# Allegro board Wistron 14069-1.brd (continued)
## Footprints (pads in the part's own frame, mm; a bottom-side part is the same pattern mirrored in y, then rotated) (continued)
SKTBGA1151R754612-UH369
  round 0.254 hole 3.81 unplated: (-35.21,0) (25.81,18) (25.81,-18)
  round 0.508 smd: A4(-16.187,18.288) A5(-15.273,18.288) AT40(18.931,-14.63) AU1(-18.931,-14.63) AU39(18.016,-15.545) AU40(18.931,-15.545) AV1(-18.931,-15.545) AV2(-18.016,-15.545) AV38(17.102,-16.459) AV39(18.016,-16.459) AW2(-18.016,-16.459) AW3(-17.102,-16.459) AW37(16.187,-17.374) AW38(17.102,-17.374) AY3(-17.102,-17.374) AY4(-16.187,-17.374) B3(-17.102,17.374) B4(-16.187,17.374) B37(16.187,16.459) B38(17.102,16.459) B39(18.016,16.459) C2(-18.016,16.459) C3(-17.102,16.459) C39(18.016,15.545) C40(18.931,15.545) D1(-18.931,15.545) D2(-18.016,15.545) D40(18.931,14.63) E40(18.931,13.716)
  round 0.429 smd: A6(-14.359,18.288) A7(-13.444,18.288) A25(3.015,18.288) A26(3.929,18.288) A27(4.844,18.288) A28(5.758,18.288) A29(6.673,18.288) A30(7.587,18.288) AA5(-15.273,0) AA6(-14.359,0) AA7(-13.444,0) AA8(-12.53,0) AA33(12.53,-0.914) AA34(13.444,-0.914) AA35(14.359,-0.914) AA36(15.273,-0.914) AA37(16.187,-0.914) AA38(17.102,-0.914) AB5(-15.273,-0.914) AB6(-14.359,-0.914) AB7(-13.444,-0.914) AB8(-12.53,-0.914) AB33(12.53,-1.829) AB34(13.444,-1.829) AB35(14.359,-1.829) AB36(15.273,-1.829) AB37(16.187,-1.829) AC5(-15.273,-1.829) AC6(-14.359,-1.829) AC7(-13.444,-1.829) AC8(-12.53,-1.829) AC33(12.53,-2.743) AC34(13.444,-2.743) AC35(14.359,-2.743) AC36(15.273,-2.743) AC37(16.187,-2.743) AD3(-17.102,-2.743) AD4(-16.187,-2.743) AD5(-15.273,-2.743) AD6(-14.359,-2.743) AD7(-13.444,-2.743) AD8(-12.53,-2.743) AD33(12.53,-3.658) AD34(13.444,-3.658) AD35(14.359,-3.658) AD36(15.273,-3.658) AD37(16.187,-3.658) AE3(-17.102,-3.658) AE4(-16.187,-3.658) AE5(-15.273,-3.658) AE6(-14.359,-3.658) AE7(-13.444,-3.658) AE8(-12.53,-3.658) AE33(12.53,-4.572) AE34(13.444,-4.572) AE35(14.359,-4.572) AE36(15.273,-4.572) AE37(16.187,-4.572) AE38(17.102,-4.572) AF4(-16.187,-4.572) AF5(-15.273,-4.572) AF6(-14.359,-4.572) AF7(-13.444,-4.572) AF8(-12.53,-4.572) AF33(12.53,-5.486) AF34(13.444,-5.486) AF35(14.359,-5.486) AF36(15.273,-5.486) AF37(16.187,-5.486) AF38(17.102,-5.486) AG4(-16.187,-5.486) AG5(-15.273,-5.486) AG6(-14.359,-5.486) AG7(-13.444,-5.486) AG8(-12.53,-5.486) AG33(12.53,-6.401) AG34(13.444,-6.401) AG35(14.359,-6.401) AG36(15.273,-6.401) AG37(16.187,-6.401) AG38(17.102,-6.401) AH3(-17.102,-6.401) AH4(-16.187,-6.401) AH5(-15.273,-6.401) AH6(-14.359,-6.401) AH7(-13.444,-6.401) AH8(-12.53,-6.401) AH33(12.53,-7.315) AH34(13.444,-7.315) AH35(14.359,-7.315) AH36(15.273,-7.315) AH37(16.187,-7.315) AH38(17.102,-7.315) AJ3(-17.102,-7.315) AJ4(-16.187,-7.315) AJ5(-15.273,-7.315) AJ6(-14.359,-7.315) AJ7(-13.444,-7.315) AJ8(-12.53,-7.315) AJ9(-11.615,-7.315) AJ11(-7.587,-8.23) AJ12(-6.673,-8.23) AJ13(-5.758,-8.23) AJ14(-4.844,-8.23) AJ15(-3.929,-8.23) AJ16(-3.015,-8.23) AJ17(-2.101,-8.23) AJ18(-1.186,-8.23) AJ19(-0.272,-8.23) AJ20(0.643,-8.23) AJ21(1.557,-8.23) AJ22(2.471,-8.23) AJ23(3.386,-8.23) AJ24(4.3,-8.23) AJ25(5.215,-8.23) AJ26(6.129,-8.23) AJ27(7.043,-8.23) AJ28(7.958,-8.23) AJ29(8.872,-8.23) AJ30(9.787,-8.23) AJ31(10.701,-8.23) AJ32(11.615,-8.23) AJ33(12.53,-8.23) AJ34(13.444,-8.23) AJ35(14.359,-8.23) AJ36(15.273,-8.23) AJ37(16.187,-8.23) AJ38(17.102,-8.23) AK3(-17.102,-8.23) AK4(-16.187,-8.23) AK5(-15.273,-8.23) AK6(-14.359,-8.23) AK7(-13.444,-8.23) AK8(-12.53,-8.23) AK9(-11.615,-8.23) AK10(-10.701,-8.23) AK11(-7.587,-9.144) AK12(-6.673,-9.144) AK13(-5.758,-9.144) AK14(-4.844,-9.144) AK15(-3.929,-9.144) AK16(-3.015,-9.144) AK17(-2.101,-9.144) AK18(-1.186,-9.144) AK19(-0.272,-9.144) AK20(0.643,-9.144) AK21(1.557,-9.144) AK22(2.471,-9.144) AK23(3.386,-9.144) AK24(4.3,-9.144) AK25(5.215,-9.144) AK26(6.129,-9.144) AK27(7.043,-9.144) AK28(7.958,-9.144) AK29(8.872,-9.144) AK30(9.787,-9.144) AK31(10.701,-9.144) AK32(11.615,-9.144) AK33(12.53,-9.144) AK34(13.444,-9.144) AK35(14.359,-9.144) AK36(15.273,-9.144) AK37(16.187,-9.144) AK38(17.102,-9.144) AL3(-17.102,-9.144) AL4(-16.187,-9.144) AL5(-15.273,-9.144) AL6(-14.359,-9.144) AL7(-13.444,-9.144) AL8(-12.53,-9.144) AL9(-11.615,-9.144) AL10(-10.701,-9.144) AL11(-7.587,-10.058) AL12(-6.673,-10.058) AL13(-5.758,-10.058) AL14(-4.844,-10.058) AL15(-3.929,-10.058) AL16(-3.015,-10.058) AL17(-2.101,-10.058) AL18(-1.186,-10.058) AL19(-0.272,-10.058) AL20(0.643,-10.058) AL21(1.557,-10.058) AL22(2.471,-10.058) AL23(3.386,-10.058) AL24(4.3,-10.058) AL25(5.215,-10.058) AL26(6.129,-10.058) AL27(7.043,-10.058) AL28(7.958,-10.058) AL29(8.872,-10.058) AL30(9.787,-10.058) AL31(10.701,-10.058) AL32(11.615,-10.058) AL33(12.53,-10.058) AL34(13.444,-10.058) AL35(14.359,-10.058) AL36(15.273,-10.058) AL37(16.187,-10.058) AL38(17.102,-10.058) AM3(-17.102,-10.058) AM4(-16.187,-10.058) AM5(-15.273,-10.058) AM6(-14.359,-10.058) AM7(-13.444,-10.058) AM8(-12.53,-10.058) AM9(-11.615,-10.058) AM10(-10.701,-10.058) AM11(-7.587,-10.973) AM12(-6.673,-10.973) AM13(-5.758,-10.973) AM14(-4.844,-10.973) AM15(-3.929,-10.973) AM16(-3.015,-10.973) AM17(-2.101,-10.973) AM18(-1.186,-10.973) AM19(-0.272,-10.973) AM20(0.643,-10.973) AM21(1.557,-10.973) AM22(2.471,-10.973) AM23(3.386,-10.973) AM24(4.3,-10.973) AM25(5.215,-10.973) AM26(6.129,-10.973) AM27(7.043,-10.973) AM28(7.958,-10.973) AM29(8.872,-10.973) AM30(9.787,-10.973) AM31(10.701,-10.973) AM32(11.615,-10.973) AM33(12.53,-10.973) AM34(13.444,-10.973) AM35(14.359,-10.973) AM36(15.273,-10.973) AM37(16.187,-10.973) AM38(17.102,-10.973) AN3(-17.102,-10.973) AN4(-16.187,-10.973) AN5(-15.273,-10.973) AN6(-14.359,-10.973) AN7(-13.444,-10.973) AN8(-12.53,-10.973) AN9(-11.615,-10.973) AN10(-10.701,-10.973) AN11(-7.587,-11.887) AN12(-6.673,-11.887) AN13(-5.758,-11.887) AN14(-4.844,-11.887) AN15(-3.929,-11.887) AN16(-3.015,-11.887) AN17(-2.101,-11.887) AN18(-1.186,-11.887) AN19(-0.272,-11.887) AN20(0.643,-11.887) AN21(1.557,-11.887) AN22(2.471,-11.887) AN23(3.386,-11.887) AN24(4.3,-11.887) AN25(5.215,-11.887) AN26(6.129,-11.887) AN27(7.043,-11.887) AN28(7.958,-11.887) AN29(8.872,-11.887) AN30(9.787,-11.887) AN31(10.701,-11.887) AN32(11.615,-11.887) AN33(12.53,-11.887) AN34(13.444,-11.887) AN35(14.359,-11.887) AN36(15.273,-11.887) AN37(16.187,-11.887) AN38(17.102,-11.887) AP3(-17.102,-11.887) AP4(-16.187,-11.887) AP5(-15.273,-11.887) AP6(-14.359,-11.887) AP7(-13.444,-11.887) AP8(-12.53,-11.887) AP9(-11.615,-11.887) AP10(-10.701,-11.887) AP11(-7.587,-12.802) AP12(-6.673,-12.802) AP13(-5.758,-12.802) AP14(-4.844,-12.802) AP15(-3.929,-12.802) AP16(-3.015,-12.802) AP17(-2.101,-12.802) AP18(-1.186,-12.802) AP19(-0.272,-12.802) AP20(0.643,-12.802) AP21(1.557,-12.802) AP22(2.471,-12.802) AP23(3.386,-12.802) AP24(4.3,-12.802) AP25(5.215,-12.802) AP26(6.129,-12.802) AP27(7.043,-12.802) AP28(7.958,-12.802) AP29(8.872,-12.802) AP30(9.787,-12.802) AP31(10.701,-12.802) AP32(11.615,-12.802) AP33(12.53,-12.802) AP34(13.444,-12.802) AP35(14.359,-12.802) AP36(15.273,-12.802) AP37(16.187,-12.802) AP38(17.102,-12.802) AR3(-17.102,-12.802) AR4(-16.187,-12.802) AR5(-15.273,-12.802) AR6(-14.359,-12.802) AR7(-13.444,-12.802) AR8(-12.53,-12.802) AR9(-11.615,-12.802) AR10(-10.701,-12.802) AR11(-7.587,-13.716) AR12(-6.673,-13.716) AR13(-5.758,-13.716) AR14(-4.844,-13.716) AR15(-3.929,-13.716) AR16(-3.015,-13.716) AR17(-2.101,-13.716) AR18(-1.186,-13.716) AR19(-0.272,-13.716) AR20(0.643,-13.716) AR21(1.557,-13.716) AR22(2.471,-13.716) AR23(3.386,-13.716) AR24(4.3,-13.716) AR25(5.215,-13.716) AR26(6.129,-13.716) AR27(7.043,-13.716) AR28(7.958,-13.716) AR29(8.872,-13.716) AR30(9.787,-13.716) AR31(10.701,-13.716) AR32(11.615,-13.716) AR33(12.53,-13.716) AR34(13.444,-13.716) AR35(14.359,-13.716) AR36(15.273,-13.716) AR37(16.187,-13.716) AR38(17.102,-13.716) AT3(-17.102,-13.716) AT4(-16.187,-13.716) AT5(-15.273,-13.716) AT6(-14.359,-13.716) AT7(-13.444,-13.716) AT8(-12.53,-13.716) AT9(-11.615,-13.716) AT10(-10.701,-13.716) AT11(-7.587,-14.63) AT12(-6.673,-14.63) AT13(-5.758,-14.63) AT14(-4.844,-14.63) AT15(-3.929,-14.63) AT16(-3.015,-14.63) AT17(-2.101,-14.63) AT18(-1.186,-14.63) AT19(-0.272,-14.63) AT20(0.643,-14.63) AT21(1.557,-14.63) AT22(2.471,-14.63) AT23(3.386,-14.63) AT24(4.3,-14.63) AT25(5.215,-14.63) AT26(6.129,-14.63) AT27(7.043,-14.63) AT28(7.958,-14.63) AT29(8.872,-14.63) AT30(9.787,-14.63) AT31(10.701,-14.63) AT32(11.615,-14.63) AT33(12.53,-14.63) AT34(13.444,-14.63) AT35(14.359,-14.63) AT36(15.273,-14.63) AT37(16.187,-14.63) AT38(17.102,-14.63) AU3(-17.102,-14.63) AU4(-16.187,-14.63) AU5(-15.273,-14.63) AU6(-14.359,-14.63) AU7(-13.444,-14.63) AU8(-12.53,-14.63) AU9(-11.615,-14.63) AU10(-10.701,-14.63) AU11(-7.587,-15.545) AU12(-6.673,-15.545) AU13(-5.758,-15.545) AU14(-4.844,-15.545) AU15(-3.929,-15.545) AU16(-3.015,-15.545) AU17(-2.101,-15.545) AU18(-1.186,-15.545) AU19(-0.272,-15.545) AU20(0.643,-15.545) AU21(1.557,-15.545) AU24(4.3,-15.545) AU25(5.215,-15.545) AU26(6.129,-15.545) AU27(7.043,-15.545) AU28(7.958,-15.545) AU29(8.872,-15.545) AU30(9.787,-15.545) AU31(10.701,-15.545) AU32(11.615,-15.545) AU33(12.53,-15.545) AU34(13.444,-15.545) AU35(14.359,-15.545) AU36(15.273,-15.545) AU37(16.187,-15.545) AU38(17.102,-15.545) AV3(-17.102,-15.545) AV4(-16.187,-15.545) AV5(-15.273,-15.545) AV6(-14.359,-15.545) AV7(-13.444,-15.545) AV8(-12.53,-15.545) AV9(-11.615,-15.545) AV10(-10.701,-15.545) AV11(-7.587,-16.459) AV12(-6.673,-16.459) AV13(-5.758,-16.459) AV14(-4.844,-16.459) AV24(4.3,-16.459) AV25(5.215,-16.459) AV28(7.958,-16.459) AV29(8.872,-16.459) AV37(16.187,-16.459) AW4(-16.187,-16.459) AW9(-11.615,-16.459) AW10(-10.701,-16.459) AW11(-7.587,-17.374) AW12(-6.673,-17.374) AW13(-5.758,-17.374) AW14(-4.844,-17.374) AY10(-10.701,-17.374) B5(-15.273,17.374) B6(-14.359,17.374) B7(-13.444,17.374) B25(3.015,17.374) B26(3.929,17.374) B27(4.844,17.374) B28(5.758,17.374) B29(6.673,17.374) B30(7.587,17.374) B31(10.701,16.459) B32(11.615,16.459) B33(12.53,16.459) B34(13.444,16.459) B35(14.359,16.459) B36(15.273,16.459) C4(-16.187,16.459) C5(-15.273,16.459) C6(-14.359,16.459) C7(-13.444,16.459) C8(-12.53,16.459) C9(-11.615,16.459) C12(-8.872,16.459) C13(-7.958,16.459) C14(-7.043,16.459) C15(-6.129,16.459) C16(-5.215,16.459) C17(-4.3,16.459) C25(3.015,16.459) C26(3.929,16.459) C27(4.844,16.459) C28(5.758,16.459) C29(6.673,16.459) C30(7.587,16.459) C31(10.701,15.545) C32(11.615,15.545) C33(12.53,15.545) C34(13.444,15.545) C35(14.359,15.545) C36(15.273,15.545) C37(16.187,15.545) C38(17.102,15.545) D3(-17.102,15.545) D4(-16.187,15.545) D5(-15.273,15.545) D6(-14.359,15.545) D7(-13.444,15.545) D8(-12.53,15.545) D9(-11.615,15.545) D10(-10.701,15.545) D11(-9.787,15.545) D12(-8.872,15.545) D13(-7.958,15.545) D14(-7.043,15.545) D15(-6.129,15.545) D16(-5.215,15.545) D17(-4.3,15.545) D24(2.101,15.545) D25(3.015,15.545) D26(3.929,15.545) D27(4.844,15.545) D28(5.758,15.545) D29(6.673,15.545) D30(7.587,15.545) D31(10.701,14.63) D32(11.615,14.63) D33(12.53,14.63) D34(13.444,14.63) D35(14.359,14.63) D36(15.273,14.63) D37(16.187,14.63) D38(17.102,14.63) D39(18.016,14.63) E3(-17.102,14.63) E4(-16.187,14.63) E5(-15.273,14.63) E6(-14.359,14.63) E7(-13.444,14.63) E8(-12.53,14.63) E9(-11.615,14.63) E10(-10.701,14.63) E11(-9.787,14.63) E12(-8.872,14.63) E13(-7.958,14.63) E14(-7.043,14.63) E15(-6.129,14.63) E16(-5.215,14.63) E17(-4.3,14.63) E18(-3.386,14.63) E19(-2.471,14.63) E21(-0.643,14.63) E23(1.186,14.63) E24(2.101,14.63) E25(3.015,14.63) E26(3.929,14.63) E27(4.844,14.63) E28(5.758,14.63) E29(6.673,14.63) E30(7.587,14.63) E31(10.701,13.716) E32(11.615,13.716) E33(12.53,13.716) E34(13.444,13.716) E35(14.359,13.716) E36(15.273,13.716) E37(16.187,13.716) E38(17.102,13.716) E39(18.016,13.716) F4(-16.187,13.716) F5(-15.273,13.716) F6(-14.359,13.716) F7(-13.444,13.716) F8(-12.53,13.716) F9(-11.615,13.716) F10(-10.701,13.716) F11(-9.787,13.716) F12(-8.872,13.716) F13(-7.958,13.716) F14(-7.043,13.716) F15(-6.129,13.716) F16(-5.215,13.716) F17(-4.3,13.716) F18(-3.386,13.716) F19(-2.471,13.716) F20(-1.557,13.716) F21(-0.643,13.716) F22(0.272,13.716) F23(1.186,13.716) F24(2.101,13.716) F25(3.015,13.716) F26(3.929,13.716) F27(4.844,13.716) F28(5.758,13.716) F29(6.673,13.716) F30(7.587,13.716) F31(10.701,12.802) F32(11.615,12.802) F33(12.53,12.802) F34(13.444,12.802) F35(14.359,12.802) F36(15.273,12.802) F37(16.187,12.802) F38(17.102,12.802) F39(18.016,12.802) F40(18.931,12.802) G3(-17.102,12.802) G4(-16.187,12.802) G5(-15.273,12.802) G6(-14.359,12.802) G7(-13.444,12.802) G8(-12.53,12.802) G9(-11.615,12.802) G10(-10.701,12.802) G11(-9.787,12.802) G12(-8.872,12.802) G13(-7.958,12.802) G14(-7.043,12.802) G15(-6.129,12.802) G16(-5.215,12.802) G17(-4.3,12.802) G18(-3.386,12.802) G19(-2.471,12.802) G20(-1.557,12.802) G21(-0.643,12.802) G22(0.272,12.802) G23(1.186,12.802) G24(2.101,12.802) G25(3.015,12.802) G26(3.929,12.802) G27(4.844,12.802) G28(5.758,12.802) G29(6.673,12.802) G30(7.587,12.802) G31(10.701,11.887) G32(11.615,11.887) G33(12.53,11.887) G34(13.444,11.887) G35(14.359,11.887) G36(15.273,11.887) G37(16.187,11.887) G38(17.102,11.887) G39(18.016,11.887) G40(18.931,11.887) H4(-16.187,11.887) H5(-15.273,11.887) H6(-14.359,11.887) H7(-13.444,11.887) H8(-12.53,11.887) H9(-11.615,11.887) H10(-10.701,11.887) H11(-9.787,11.887) H12(-8.872,11.887) H13(-7.958,11.887) H14(-7.043,11.887) H15(-6.129,11.887) H16(-5.215,11.887) H17(-4.3,11.887) H18(-3.386,11.887) H19(-2.471,11.887) H20(-1.557,11.887) H21(-0.643,11.887) H22(0.272,11.887) H23(1.186,11.887) H24(2.101,11.887) H25(3.015,11.887) H26(3.929,11.887) H27(4.844,11.887) H28(5.758,11.887) H29(6.673,11.887) H30(7.587,11.887) H31(10.701,10.973) H32(11.615,10.973) H33(12.53,10.973) H34(13.444,10.973) H35(14.359,10.973) H36(15.273,10.973) H37(16.187,10.973) H38(17.102,10.973) H39(18.016,10.973) H40(18.931,10.973) J3(-17.102,10.973) J4(-16.187,10.973) J5(-15.273,10.973) J6(-14.359,10.973) J7(-13.444,10.973) J8(-12.53,10.973) J9(-11.615,10.973) J10(-10.701,10.973) J11(-9.787,10.973) J12(-8.872,10.973) J13(-7.958,10.973) J14(-7.043,10.973) J15(-6.129,10.973) J16(-5.215,10.973) J17(-4.3,10.973) J18(-3.386,10.973) J19(-2.471,10.973) J20(-1.557,10.973) J21(-0.643,10.973) J22(0.272,10.973) J23(1.186,10.973) J24(2.101,10.973) J25(3.015,10.973) J26(3.929,10.973) J27(4.844,10.973) J28(5.758,10.973) J29(6.673,10.973) J30(7.587,10.973) J31(10.701,10.058) J32(11.615,10.058) J33(12.53,10.058) J34(13.444,10.058) J35(14.359,10.058) J36(15.273,10.058) J37(16.187,10.058) J38(17.102,10.058) J39(18.016,10.058) J40(18.931,10.058) K4(-16.187,10.058) K5(-15.273,10.058) K6(-14.359,10.058) K7(-13.444,10.058) K8(-12.53,10.058) K9(-11.615,10.058) K10(-10.701,10.058) K11(-9.787,10.058) K12(-8.872,10.058) K13(-7.958,10.058) K14(-7.043,10.058) K15(-6.129,10.058) K16(-5.215,10.058) K17(-4.3,10.058) K18(-3.386,10.058) K19(-2.471,10.058) K20(-1.557,10.058) K21(-0.643,10.058) K22(0.272,10.058) K23(1.186,10.058) K24(2.101,10.058) K25(3.015,10.058) K26(3.929,10.058) K27(4.844,10.058) K28(5.758,10.058) K29(6.673,10.058) K30(7.587,10.058) K31(10.701,9.144) K32(11.615,9.144) K33(12.53,9.144) K34(13.444,9.144) K35(14.359,9.144) K36(15.273,9.144) K37(16.187,9.144) K38(17.102,9.144) K39(18.016,9.144) K40(18.931,9.144) L3(-17.102,9.144) L4(-16.187,9.144) L5(-15.273,9.144) L6(-14.359,9.144) L7(-13.444,9.144) L8(-12.53,9.144) L9(-11.615,9.144) L10(-10.701,9.144) L11(-9.787,9.144) L12(-8.872,9.144) L13(-7.958,9.144) L14(-7.043,9.144) L15(-6.129,9.144) L16(-5.215,9.144) L17(-4.3,9.144) L18(-3.386,9.144) L19(-2.471,9.144) L20(-1.557,9.144) L21(-0.643,9.144) L22(0.272,9.144) L23(1.186,9.144) L24(2.101,9.144) L25(3.015,9.144) L26(3.929,9.144) L27(4.844,9.144) L28(5.758,9.144) L29(6.673,9.144) L30(7.587,9.144) L31(10.701,8.23) L32(11.615,8.23) L33(12.53,8.23) L34(13.444,8.23) L35(14.359,8.23) L36(15.273,8.23) L37(16.187,8.23) L38(17.102,8.23) L39(18.016,8.23) L40(18.931,8.23) M4(-16.187,8.23) M5(-15.273,8.23) M6(-14.359,8.23) M7(-13.444,8.23) M8(-12.53,8.23) M9(-11.615,8.23) M10(-10.701,8.23) M11(-9.787,8.23) M12(-8.872,8.23) M13(-7.958,8.23) M14(-7.043,8.23) M15(-6.129,8.23) M16(-5.215,8.23) M17(-4.3,8.23) M18(-3.386,8.23) M19(-2.471,8.23) M20(-1.557,8.23) M21(-0.643,8.23) M22(0.272,8.23) M23(1.186,8.23) M24(2.101,8.23) M25(3.015,8.23) M26(3.929,8.23) M27(4.844,8.23) M28(5.758,8.23) M29(6.673,8.23) M30(7.587,8.23) M32(11.615,7.315) M33(12.53,7.315) M34(13.444,7.315) M35(14.359,7.315) M36(15.273,7.315) M37(16.187,7.315) M38(17.102,7.315) M39(18.016,7.315) M40(18.931,7.315) N3(-17.102,7.315) N4(-16.187,7.315) N5(-15.273,7.315) N6(-14.359,7.315) N7(-13.444,7.315) N8(-12.53,7.315) N33(12.53,6.401) N34(13.444,6.401) N35(14.359,6.401) N36(15.273,6.401) N37(16.187,6.401) N38(17.102,6.401) N39(18.016,6.401) N40(18.931,6.401) P4(-16.187,6.401) P5(-15.273,6.401) P6(-14.359,6.401) P7(-13.444,6.401) P8(-12.53,6.401) P33(12.53,5.486) P34(13.444,5.486) P35(14.359,5.486) P36(15.273,5.486) P37(16.187,5.486) P38(17.102,5.486) P39(18.016,5.486) P40(18.931,5.486) R3(-17.102,5.486) R4(-16.187,5.486) R5(-15.273,5.486) R6(-14.359,5.486) R7(-13.444,5.486) R8(-12.53,5.486) R33(12.53,4.572) R34(13.444,4.572) R35(14.359,4.572) R36(15.273,4.572) R37(16.187,4.572) R38(17.102,4.572) R39(18.016,4.572) R40(18.931,4.572) T4(-16.187,4.572) T5(-15.273,4.572) T6(-14.359,4.572) T7(-13.444,4.572) T8(-12.53,4.572) T33(12.53,3.658) T34(13.444,3.658) T35(14.359,3.658) T36(15.273,3.658) T37(16.187,3.658) T38(17.102,3.658) T39(18.016,3.658) T40(18.931,3.658) U4(-16.187,3.658) U5(-15.273,3.658) U6(-14.359,3.658) U7(-13.444,3.658) U8(-12.53,3.658) U33(12.53,2.743) U34(13.444,2.743) U35(14.359,2.743) U36(15.273,2.743) U37(16.187,2.743) U38(17.102,2.743) U39(18.016,2.743) U40(18.931,2.743) V4(-16.187,2.743) V5(-15.273,2.743) V6(-14.359,2.743) V7(-13.444,2.743) V8(-12.53,2.743) V33(12.53,1.829) V34(13.444,1.829) V35(14.359,1.829) V36(15.273,1.829) V37(16.187,1.829) V38(17.102,1.829) V39(18.016,1.829) V40(18.931,1.829) W4(-16.187,1.829) W5(-15.273,1.829) W6(-14.359,1.829) W7(-13.444,1.829) W8(-12.53,1.829) W33(12.53,0.914) W34(13.444,0.914) W35(14.359,0.914) W36(15.273,0.914) W37(16.187,0.914) W38(17.102,0.914) Y5(-15.273,0.914) Y6(-14.359,0.914) Y7(-13.444,0.914) Y8(-12.53,0.914) Y33(12.53,0) Y34(13.444,0) Y35(14.359,0) Y36(15.273,0) Y37(16.187,0) Y38(17.102,0)
  oval 0.356x0.457 smd: A11(-9.787,18.288) A12(-8.872,18.288) A13(-7.958,18.288) A14(-7.043,18.288) A15(-6.129,18.288) A16(-5.215,18.288) A17(-4.3,18.288) A18(-3.386,18.288) A23(1.186,18.288) A24(2.101,18.288) AU22(2.471,-15.545) AU23(3.386,-15.545) AV15(-3.929,-16.459) AV16(-3.015,-16.459) AV17(-2.101,-16.459) AV18(-1.186,-16.459) AV19(-0.272,-16.459) AV20(0.643,-16.459) AV21(1.557,-16.459) AV22(2.471,-16.459) AV23(3.386,-16.459) AV26(6.129,-16.459) AV27(7.043,-16.459) AV30(9.787,-16.459) AV31(10.701,-16.459) AV32(11.615,-16.459) AV33(12.53,-16.459) AV34(13.444,-16.459) AV35(14.359,-16.459) AV36(15.273,-16.459) AW5(-15.273,-16.459) AW6(-14.359,-16.459) AW7(-13.444,-16.459) AW8(-12.53,-16.459) AW15(-3.929,-17.374) AW16(-3.015,-17.374) AW17(-2.101,-17.374) AW18(-1.186,-17.374) AW23(3.386,-17.374) AW24(4.3,-17.374) AW25(5.215,-17.374) AW26(6.129,-17.374) AW27(7.043,-17.374) AW28(7.958,-17.374) AW29(8.872,-17.374) AW30(9.787,-17.374) AW31(10.701,-17.374) AW32(11.615,-17.374) AW33(12.53,-17.374) AW34(13.444,-17.374) AW35(14.359,-17.374) AW36(15.273,-17.374) AY5(-15.273,-17.374) AY6(-14.359,-17.374) AY7(-13.444,-17.374) AY8(-12.53,-17.374) AY9(-11.615,-17.374) AY11(-7.587,-18.288) AY12(-6.673,-18.288) AY13(-5.758,-18.288) AY14(-4.844,-18.288) AY15(-3.929,-18.288) AY16(-3.015,-18.288) AY17(-2.101,-18.288) AY18(-1.186,-18.288) AY23(3.386,-18.288) AY24(4.3,-18.288) AY25(5.215,-18.288) AY26(6.129,-18.288) AY27(7.043,-18.288) AY28(7.958,-18.288) AY29(8.872,-18.288) AY30(9.787,-18.288) AY31(10.701,-18.288) B8(-12.53,17.374) B9(-11.615,17.374) B10(-10.701,17.374) B11(-9.787,17.374) B12(-8.872,17.374) B13(-7.958,17.374) B14(-7.043,17.374) B15(-6.129,17.374) B16(-5.215,17.374) B17(-4.3,17.374) B18(-3.386,17.374) B23(1.186,17.374) B24(2.101,17.374) C10(-10.701,16.459) C11(-9.787,16.459) C18(-3.386,16.459) C19(-2.471,16.459) C20(-1.557,16.459) C21(-0.643,16.459) C22(0.272,16.459) C23(1.186,16.459) C24(2.101,16.459) D18(-3.386,15.545) D19(-2.471,15.545) D20(-1.557,15.545) D21(-0.643,15.545) D22(0.272,15.545) D23(1.186,15.545) E20(-1.557,14.63) E22(0.272,14.63)
  oval 0.457x0.356 smd: AA3(-17.102,0) AA4(-16.187,0) AB3(-17.102,-0.914) AB4(-16.187,-0.914) AB38(17.102,-1.829) AB39(18.016,-1.829) AB40(18.931,-1.829) AC1(-18.931,-1.829) AC2(-18.016,-1.829) AC3(-17.102,-1.829) AC4(-16.187,-1.829) AC38(17.102,-2.743) AC39(18.016,-2.743) AC40(18.931,-2.743) AD1(-18.931,-2.743) AD2(-18.016,-2.743) AD38(17.102,-3.658) AD39(18.016,-3.658) AD40(18.931,-3.658) AE1(-18.931,-3.658) AE2(-18.016,-3.658) AE39(18.016,-4.572) AE40(18.931,-4.572) AF1(-18.931,-4.572) AF2(-18.016,-4.572) AF3(-17.102,-4.572) AF39(18.016,-5.486) AF40(18.931,-5.486) AG1(-18.931,-5.486) AG2(-18.016,-5.486) AG3(-17.102,-5.486) AG39(18.016,-6.401) AG40(18.931,-6.401) AH1(-18.931,-6.401) AH2(-18.016,-6.401) AH39(18.016,-7.315) AH40(18.931,-7.315) AJ1(-18.931,-7.315) AJ2(-18.016,-7.315) AJ39(18.016,-8.23) AJ40(18.931,-8.23) AK1(-18.931,-8.23) AK2(-18.016,-8.23) AK39(18.016,-9.144) AK40(18.931,-9.144) AL1(-18.931,-9.144) AL2(-18.016,-9.144) AL39(18.016,-10.058) AL40(18.931,-10.058) AM1(-18.931,-10.058) AM2(-18.016,-10.058) AM39(18.016,-10.973) AM40(18.931,-10.973) AN1(-18.931,-10.973) AN2(-18.016,-10.973) AN39(18.016,-11.887) AN40(18.931,-11.887) AP1(-18.931,-11.887) AP2(-18.016,-11.887) AP39(18.016,-12.802) AP40(18.931,-12.802) AR1(-18.931,-12.802) AR2(-18.016,-12.802) AR39(18.016,-13.716) AR40(18.931,-13.716) AT1(-18.931,-13.716) AT2(-18.016,-13.716) AT39(18.016,-14.63) AU2(-18.016,-14.63) E1(-18.931,14.63) E2(-18.016,14.63) F1(-18.931,13.716) F2(-18.016,13.716) F3(-17.102,13.716) G1(-18.931,12.802) G2(-18.016,12.802) H1(-18.931,11.887) H2(-18.016,11.887) H3(-17.102,11.887) J1(-18.931,10.973) J2(-18.016,10.973) K1(-18.931,10.058) K2(-18.016,10.058) K3(-17.102,10.058) L1(-18.931,9.144) L2(-18.016,9.144) M1(-18.931,8.23) M2(-18.016,8.23) M3(-17.102,8.23) N1(-18.931,7.315) N2(-18.016,7.315) P1(-18.931,6.401) P2(-18.016,6.401) P3(-17.102,6.401) R1(-18.931,5.486) R2(-18.016,5.486) T1(-18.931,4.572) T2(-18.016,4.572) T3(-17.102,4.572) U1(-18.931,3.658) U2(-18.016,3.658) U3(-17.102,3.658) V1(-18.931,2.743) V2(-18.016,2.743) V3(-17.102,2.743) W1(-18.931,1.829) W2(-18.016,1.829) W3(-17.102,1.829) Y3(-17.102,0.914) Y4(-16.187,0.914)
SMD49-6914-0403H56
  rect 1.168x0.559 smd: 1(-3.38,-0.427) 2(3.38,-0.427) 3(3.38,0.427) 4(-3.38,0.427)
SMD-ARES4-2H18-U
  rect 0.305x0.406 smd: 1(-0.25,-0.305) 2(0.25,-0.305) 3(0.25,0.305) 4(-0.25,0.305)
SMD-TO-252-4H94
  rect 1.6x2.997 smd: 1(-2.286,0) 3(2.286,0)
  rect 6.756x6.756 smd: 2(0,6.807)
SMD-TO-252-DGS6698H99
  rect 6.172x5.588 smd: D(0,6.808)
  rect 1.295x2.438 smd: G(-2.35,0) S(2.35,0)
SOD323AKH38
  rect 0.559x1.016 smd: A(0,1.143) K(0,-1.143)
SOD323AKH40
  rect 0.559x1.016 smd: A(0,1.143) K(0,-1.143)
SOD323AKH42
  rect 0.559x1.016 smd: A(0,1.143) K(0,-1.143)
SOD-523-4H28
  rect 0.559x0.864 smd: 1(0,0.778) 2(0,-0.778)
SOIC8-1H86
  rect 0.635x1.651 smd: 1(-1.905,-3.493) 2(-0.635,-3.493) 3(0.635,-3.493) 4(1.905,-3.493) 5(1.905,3.493) 6(0.635,3.493) 7(-0.635,3.493) 8(-1.905,3.493)
SOIC8H69
  rect 0.635x1.651 smd: 1(-1.905,-2.54) 2(-0.635,-2.54) 3(0.635,-2.54) 4(1.905,-2.54) 5(1.905,2.54) 6(0.635,2.54) 7(-0.635,2.54) 8(-1.905,2.54)
SOIC8H79
  rect 0.635x1.651 smd: 1(-1.905,-2.54) 2(-0.635,-2.54) 3(0.635,-2.54) 4(1.905,-2.54) 5(1.905,2.54) 6(0.635,2.54) 7(-0.635,2.54) 8(-1.905,2.54)
SOT23-2D4-312H46
  custom 0.191x0.191 smd: 1(-0.984,-0.953) 2(0.984,-0.953) 3(0,0.953)
SOT23-2D4-312H48
  custom 0.191x0.191 smd: 1(-0.984,-0.953) 2(0.984,-0.953) 3(0,0.953)
SOT23-8PH36
  rect 0.356x1.016 smd: 1(-0.975,-1.346) 2(-0.325,-1.346) 3(0.325,-1.346) 4(0.974,-1.346) 5(0.974,1.346) 6(0.325,1.346) 7(-0.325,1.346) 8(-0.975,1.346)
SOT23CBE2D4H44
  custom 0.191x0.191 smd: B(-0.984,-0.953) C(0,0.953) E(0.984,-0.953)
SOT23DGS2D4H44
  custom 0.191x0.191 smd: D(0,0.953) G(-0.984,-0.953) S(0.984,-0.953)
SOT23DGS2D4H48
  custom 0.191x0.191 smd: D(0,0.953) G(-0.984,-0.953) S(0.984,-0.953)
SOT23DGS2D8H50
  custom 0.254x0.254 smd: D(0,1.118) G(-1.016,-1.118) S(1.016,-1.118)
SOT-6H58
  rect 0.584x1.016 smd: 1(-0.953,-1.346) 2(0,-1.346) 3(0.953,-1.346) 4(0.953,1.346) 5(0,1.346) 6(-0.953,1.346)
SOT-23-5H56
  rect 0.508x1.524 smd: 1(-0.95,-1.143) 2(0,-1.143) 3(0.95,-1.143) 4(0.95,1.143) 5(-0.95,1.143)
SOT-23-9H44
  custom 0.178x0.178 smd: 1(-0.95,-0.999) 2(0.95,-0.999) 3(0,0.999)
SOT-363H44
  rect 0.406x1.016 smd: 1(-0.65,-0.94) 2(0,-0.94) 3(0.65,-0.94) 4(0.65,0.94) 5(0,0.94) 6(-0.65,0.94)
STF256R109H99
  round 6.502 hole 2.769: 1(0,0)
STF256R113-UH258
  round 6.502 hole 2.87: 1(0,0)
T11-0063-1A40-0-U
  round 1.422 hole 1.016: 1(7.62,1.27) 2(7.62,-1.27) 3(5.08,1.27) 4(5.08,-1.27) 5(2.54,1.27) 6(2.54,-1.27) 7(0,1.27) 8(0,-1.27) 9(-2.54,1.27) 11(-5.08,1.27) 12(-5.08,-1.27) 13(-7.62,1.27) 14(-7.62,-1.27)
  rect 0.025x0.025 smd: 10(-2.54,-1.27)
T12-0047-1A30-0
  round 1.118 hole 0.762: 1(3.81,-0.5) 4(0,-0.5) 7(-3.81,-0.5)
  oval 1.041x1.168 hole 0.762: 2(2.54,0.5) 3(1.27,0.5) 5(-1.27,0.5) 6(-2.54,0.5)
  round 1.778 hole 1.372: 8(6.48,0) 9(-6.48,0)
TPAD24
  round 0.61 smd: 1(0,0)
TPAD28
  round 0.711 smd: 1(0,0)
TPAD28-1-U
  round 0.711 smd: 1(0,0)
unnamed#2
  round 0.254 hole 4.039 unplated: (0,0)
WQFN56J6-G4D75H32
  rect 0.203x0.813 smd: 1(2.8,3.051) 2(2.4,3.051) 14(-2.4,3.051) 15(-2.8,3.051) 29(-2.8,-3.051) 30(-2.4,-3.051) 42(2.4,-3.051) 43(2.8,-3.051)
  rect 0.203x0.914 smd: 3(2,3.051) 4(1.6,3.051) 5(1.2,3.051) 6(0.8,3.051) 7(0.4,3.051) 8(0,3.051) 9(-0.4,3.051) 10(-0.8,3.051) 11(-1.2,3.051) 12(-1.6,3.051) 13(-2,3.051) 31(-2,-3.051) 32(-1.6,-3.051) 33(-1.2,-3.051) 34(-0.8,-3.051) 35(-0.4,-3.051) 36(0,-3.051) 37(0.4,-3.051) 38(0.8,-3.051) 39(1.2,-3.051) 40(1.6,-3.051) 41(2,-3.051)
  rect 0.914x0.203 smd: 16(-3.051,2.4) 17(-3.051,2) 18(-3.051,1.6) 19(-3.051,1.2) 20(-3.051,0.8) 21(-3.051,0.4) 22(-3.051,0) 23(-3.051,-0.4) 24(-3.051,-0.8) 25(-3.051,-1.2) 26(-3.051,-1.6) 27(-3.051,-2) 28(-3.051,-2.4) 44(3.051,-2.4) 45(3.051,-2) 46(3.051,-1.6) 47(3.051,-1.2) 48(3.051,-0.8) 49(3.051,-0.4) 50(3.051,0) 51(3.051,0.4) 52(3.051,0.8) 53(3.051,1.2) 54(3.051,1.6) 55(3.051,2) 56(3.051,2.4)
  rect 4.75x4.75 smd: 57(0,0)

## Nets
1V_CPU_CORE: C1004.1 C1005.1 C1006.1 C1007.1 C1008.1 C1009.1 C1014.1 C1015.1 C1016.1 C1017.1 C1018.1 C1019.1 C1020.1 C1025.1 C1026.1 C1027.1 C1028.1 C1030.1 C1031.1 C1032.1 C1033.1 C1034.1 C1037.1 C1038.1 C1039.1 C1040.1 C1041.1 C1042.1 C1043.1 C1044.1 C1045.1 C1046.1 C1047.1 CPU1.A25 CPU1.A26 CPU1.A27 CPU1.A28 CPU1.A29 CPU1.A30 CPU1.AJ11 CPU1.AJ12 CPU1.AJ13 CPU1.AJ14 CPU1.AJ15 CPU1.AJ16 CPU1.AJ17 CPU1.AJ18 CPU1.AJ19 CPU1.AJ20 CPU1.AJ21 CPU1.AJ22 CPU1.B25 CPU1.B27 CPU1.B29 CPU1.B31 CPU1.B32 CPU1.B33 CPU1.B34 CPU1.B35 CPU1.B36 CPU1.B37 CPU1.C25 CPU1.C26 CPU1.C27 CPU1.C28 CPU1.C29 CPU1.C30 CPU1.C32 CPU1.C34 CPU1.C36 CPU1.D25 CPU1.D27 CPU1.D29 CPU1.D31 CPU1.D32 CPU1.D33 CPU1.D34 CPU1.D35 CPU1.D36 CPU1.E24 CPU1.E25 CPU1.E26 CPU1.E27 CPU1.E28 CPU1.E29 CPU1.E30 CPU1.E32 CPU1.E34 CPU1.E36 CPU1.F23 CPU1.F24 CPU1.F25 CPU1.F27 CPU1.F29 CPU1.F31 CPU1.F32 CPU1.F33 CPU1.F34 CPU1.G23 CPU1.G24 CPU1.G25 CPU1.G26 CPU1.G27 CPU1.G28 CPU1.G29 CPU1.G30 CPU1.G32 CPU1.H22 CPU1.H23 CPU1.H25 CPU1.H27 CPU1.H29 CPU1.H31 CPU1.H32 CPU1.J21 CPU1.J22 CPU1.J23 CPU1.J24 CPU1.J25 CPU1.J26 CPU1.J27 CPU1.J28 CPU1.J29 CPU1.J30 CPU1.J31 CPU1.K16 CPU1.K18 CPU1.K20 CPU1.K21 CPU1.K23 CPU1.K25 CPU1.K27 CPU1.K29 CPU1.K31 CPU1.L14 CPU1.L15 CPU1.L16 CPU1.L17 CPU1.L18 CPU1.L19 CPU1.L20 CPU1.L21 CPU1.L22 CPU1.L23 CPU1.L24 CPU1.L25 CPU1.L26 CPU1.L27 CPU1.L28 CPU1.L29 CPU1.L30 CPU1.M13 CPU1.M14 CPU1.M16 CPU1.M18 CPU1.M20 CPU1.M22 CPU1.M24 CPU1.M26 CPU1.M28 CPU1.M30 G7901.1 PG4703.1 PG4704.1 PG4706.1 PG5204.1 PL4701.2 PL4702.2 PL4703.2 PL4704.2 PR4616.2 PT4701.1 PT4703.1 PT4704.1 PT4705.1 PT4706.1 R73.1
1V_PRIME_PCH_FUSE_SX: PCH1.AL22 R2104.1
1V_S5: C2309.1 C2319.1 C2320.1 C2321.1 PCH1.AA23 PCH1.AA26 PCH1.AA28 PCH1.AC17 PCH1.AC23 PCH1.AC26 PCH1.AC28 PCH1.AD15 PCH1.AE23 PCH1.AE26 PCH1.AJ20 PCH1.AJ21 PCH1.AJ23 PCH1.AJ25 PCH1.N17 PCH1.R17 PCH1.R19 PCH1.U20 PCH1.U21 PCH1.U23 PCH1.U25 PCH1.U26 PCH1.V17 PCH1.V26 PCH1.V28 PCH1.Y23 PCH1.Y25 PR5101.2 PR5104.1 PR5114.2 PR5115.2 PR5116.2 PR5117.2 Q2.D R704.1 R1803.1 R2104.2 R2301.1 R2302.1 R2303.1 R9918.2 XDP1.43 XDP1.44
1V_VCCAMPHYPLL_S5: C2302.1 C2303.1 C2314.1 PCH1.A43 PCH1.B43 PCH1.C44 PCH1.C45 R2302.2
1V_VCCAPLL_S5: C2304.1 C2305.1 PCH1.AJ5 PCH1.AL5 PCH1.AN19 R2303.2
1V_VCCDSW_PCH: C2312.1 PCH1.BA29
1V_VCCF24_S5: C2306.1 C2307.1 C2315.1 PCH1.K2 PCH1.K3 R2301.2
1V_VCCGT_S0: C1054.1 C1055.1 C1056.1 C1057.1 C1058.1 C1059.1 C1060.1 C1061.1 C1062.1 C1063.1 C1064.1 C1065.1 C1066.1 C1067.1 C1068.1 C1069.1 C1070.1 C1071.1 C1072.1 C1073.1 C1074.1 C1075.1 C1077.1 C1079.1 C1081.1 C1084.1 C1085.1 C1086.1 C1087.1 C1088.1 C1089.1 CPU1.AA34 CPU1.AA35 CPU1.AA36 CPU1.AA37 CPU1.AA38 CPU1.AB33 CPU1.AB34 CPU1.G36 CPU1.G37 CPU1.G38 CPU1.G39 CPU1.G40 CPU1.H36 CPU1.H38 CPU1.H40 CPU1.J36 CPU1.J37 CPU1.J38 CPU1.J39 CPU1.J40 CPU1.K36 CPU1.K38 CPU1.K40 CPU1.L34 CPU1.L35 CPU1.L36 CPU1.L37 CPU1.L38 CPU1.L39 CPU1.L40 CPU1.M33 CPU1.M34 CPU1.M36 CPU1.M38 CPU1.M40 CPU1.N34 CPU1.N35 CPU1.N36 CPU1.N37 CPU1.N38 CPU1.N39 CPU1.N40 CPU1.P33 CPU1.P34 CPU1.P36 CPU1.P38 CPU1.P40 CPU1.R34 CPU1.R35 CPU1.R36 CPU1.R37 CPU1.R38 CPU1.R39 CPU1.R40 CPU1.T33 CPU1.T34 CPU1.T36 CPU1.T38 CPU1.T40 CPU1.U34 CPU1.U35 CPU1.U36 CPU1.U37 CPU1.U38 CPU1.U39 CPU1.U40 CPU1.V33 CPU1.V34 CPU1.V36 CPU1.V38 CPU1.V40 CPU1.W34 CPU1.W35 CPU1.W36 CPU1.W37 CPU1.W38 CPU1.Y33 CPU1.Y34 CPU1.Y36 CPU1.Y38 PG4802.1 PG4804.1 PL4801.2 PL4802.2 PR4635.2 PT4801.1 PT4803.1 PT4804.1 PT4805.1 PT4806.1
3V_BATIN_SX: C2503.2 D2502.1 R2514.2 R2516.1
3V_VBAT1_G3: BT1.1 R2515.1 TP_VBAT_1.1
3V_VBAT1_G3_R: D2502.2 R2515.2 TP_VBAT_2.1
3V_VRTC_G3: C2504.1 D2502.3 R1510.2 R2046.1 R2049.2 R2304.1 R7925.2
5V_AUX: C3508.1 C3509.1 C3809.1 C3810.1 C3813.1 D2702.A L2702.2 LEDH1.11 PC5002.1 PD5002.A PD5101.A PG4699.2 PR4604.1 PR4665.2 PR4694.2 PR5002.1 PR5105.1 PR5112.2 PR5202.1 PR5203.1 PR5311.2 PU5002.12 Q3507.D Q3508.D Q3509.D Q6403.E Q6405.E Q6407.E Q6806.E R77.1 R78.1 R476.2 R544.1 R2930.1 R2937.1 R2954.1 R3519.2 R3520.2 R5201.1 R6413.1 R6424.1 R6426.1 R6427.1 R6821.1 R7968.2 U3601.1 U3601.2 U3603.1 U3603.2 U3604.1 U3604.2 U3605.5 U3606.5 U3607.1 U3607.2 U3608.5
5V_AUX_EN: Q3516.D R3501.2 R3516.2 R3524.2 R4202.2
5V_AUX_EN_INV: Q3512.G Q3514.D Q3515.C Q3516.G R3522.2
5V_AUX_WPWR: C3709.1 C3714.1 R3705.1 TC3701.1 U3608.1 WPWR1.1
5V_DDCHDMI_S0: C5611.2 D5601.K R5612.1 R5613.1
5V_DUAL_USB_F: C3402.2 Q3109.S R3403.1 R3416.1 U3401.1 U3402.5 U3402.6 U3402.7 U3402.8
5V_DUAL_USBCHAR_F: C3401.1 C3403.1 Q3109.D R80.1 TC3401.1 U3401.12 USB3F1.1
5V_HDMICON_S0: C5610.2 HDMI1.18 L5601.1
5V_HDMICON_S0_L: F5601.2 L5601.2
5V_LDOIN_SIO_SX: C2730.1 C2731.1 L2702.1 R2715.1 U2701.29
5V_RR: C2918.1 C2919.1 L2901.1 SPK1.8
5V_S0: ATX1.4 ATX1.6 ATX1.21 ATX1.22 ATX1.23 BUZ1.1 C3507.2 C4311.1 C5609.2 D5601.A F5601.1 L2901.2 Q3507.S Q5701.G R3521.2 R4306.1 R4309.1 R5701.1 R5703.1 R6402.1 R6411.1 R6824.1 R7963.2 R64013.2 U3402.1
5V_SB: ATX1.9 C364.1 C365.1 C3504.1 C4304.2 C4305.2 Q3508.S Q3509.S R2955.1 R3159.1 R3167.2 R3516.1 R3519.1 R3520.1 R3522.1 R3524.1 R3527.1 R4303.1 R4311.1 R6406.1 U16.3 U3402.3
5V_USB20_RJUSB: C3605.1 C3606.1 R3601.1 TC3601.1 U2RJ1.U1 U2RJ1.U5 U3601.7 U3601.8 U3602.5
5V_USB20H2: C3702.1 C3703.1 C3710.1 R3701.1 TC3702.1 U3603.7 U3603.8 U3701.5 USB2F2.9 USB2F2.10
5V_USB20H3: C3704.1 C3705.1 C3708.1 CRF1.5 R3703.1 U3604.7 U3604.8 U3702.5
5V_USB30H1: C3902.1 C3903.1 C3904.1 R3914.1 R3916.1 R3917.2 TC3901.1 U3607.7 U3607.8 U3903.5 USB3F1.19
5V_USB30P1: C3802.1 C3803.1 C3805.1 R3813.1 R3814.1 TC3801.1 U3606.1 U3804.5 USB3R1.1 USB3R1.10
5V_USB30P2: C3804.1 C3806.1 C3807.1 TC3802.1 U3605.1 U3803.5 USB3R2.1 USB3R2.10
12V_CPU_S0: ATX2.3 ATX2.4 C4307.1 PR4684.2 PR4720.2 PR4721.2 PR4722.2 PR4723.2 PR4724.2 PR4725.2 PR4802.2 PR4803.2 PR4805.2 PR4806.2 PR4807.2 PR5217.2 PR5218.2 PR5219.2 PR5302.2 PR5303.2
12V_S0: ATX1.10 ATX1.11 C2602.1 C2603.1 C2605.1 C4310.1 C9310.1 C9311.1 C9312.1 C9402.1 C9403.1 C9413.1 C9414.1 FANC1.2 PCIE1.A2 PCIE1.A3 PCIE1.B1 PCIE1.B2 PCIE1.B3 PCIE2.A2 PCIE2.A3 PCIE2.B1 PCIE2.B2 PCIE2.B3 PCIE16.A2 PCIE16.A3 PCIE16.B1 PCIE16.B2 PCIE16.B3 PD5001.A PD5102.A Q2602.E Q2603.E Q2604.E Q2605.E R523.1 R866.1 R2602.1 R2608.1 R2609.2 R2618.1 R2621.2 R2622.1 R2625.1 R3523.2 R4308.1 R5702.1 R5704.1 R7952.2 TC9302.1 TC9401.1 TC9402.1
+5V_AUX_EN: C3507.1 Q3507.G R3502.1
+5V_AUX_EN_12V: Q3512.D R3418.1 R3502.2 R3521.1 R3523.1 R4203.2
+VCCFUSEPRG: CPU1.V6 R74.2
+VCCPLL_OC_R: CPU1.AJ9 R802.1
-12V_S0: ATX1.14 C4308.1
AGND: AUDF1.1 AUDR1.1 AUDR1.4 AUDR1.24 AUDR1.34 C2717.2 C2718.2 C2719.2 C2720.2 C2724.2 C2725.2 C2726.2 C2727.2 C2730.2 C2731.2 C2733.2 C2734.2 C2918.2 C2919.2 C2920.2 C2921.2 C2934.1 C2935.2 C2936.1 C2937.2 C3001.2 C3002.2 C3003.2 C3004.2 C3005.2 C3006.2 H6.1 H6.2 H6.3 H6.4 H6.5 H6.6 H6.7 H6.8 Q2901.1 Q2901.4 Q2902.1 Q2902.4 Q2903.E Q3001.1 Q3001.4 Q3002.1 Q3002.4 Q3003.1 Q3003.4 R2701.2 R2705.2 R2706.2 R2707.2 R2716.2 R2936.1 R2943.2 R2946.2 R3006.2 R3007.2 SPK1.2 SPK1.5 SPK1.6 U2701.26 U2701.42
AVDD2: C2724.1 C2725.1 C2726.1 C2727.1 U2701.25 U2701.38
